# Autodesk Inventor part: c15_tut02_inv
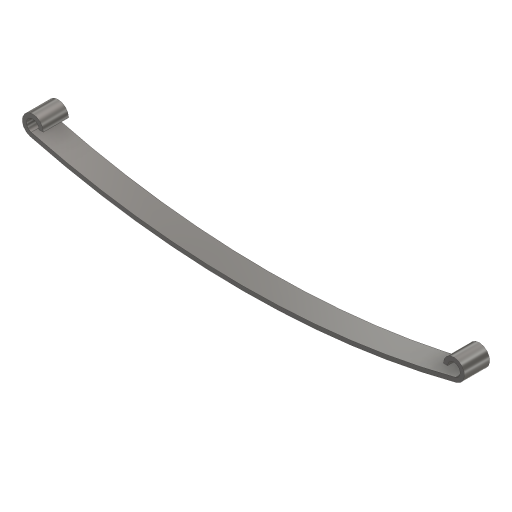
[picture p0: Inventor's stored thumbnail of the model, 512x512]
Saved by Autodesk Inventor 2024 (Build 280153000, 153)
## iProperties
Created: 2017-05
Part Number: c15_tut02_inv
Material: Steel, Mild
Document SubType Name: Modeling
Designer: CADCIM 00
Mass: 5.6491 g
Surface Area: 16.9114 cm^2
Volume: 0.71963 cm^3
Density: 7.85 g/cm^3
Appearance: Semi-Polished
Author: CADCIM 00
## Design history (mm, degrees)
sketch "Sketch1"
  geometry: L1 (0, 0)-(0, 18.068); L2 (48.5, 8.9)-(47.5, 8.9); L3 (-48.5, 8.9)-(-47.5, 8.9); A1 r 200 centre (0, 201) between (-50.378, 7.449) and (50.378, 7.449); A2 r 201 centre (0, 201) between (-50.63, 6.481) and (50.63, 6.481); A3 r 1.5 centre (50, 8.9) between (50.378, 7.449) and (48.5, 8.9); A4 r 2.5 centre (50, 8.9) between (50.63, 6.481) and (47.5, 8.9); A5 r 1.5 centre (-50, 8.9) between (-48.5, 8.9) and (-50.378, 7.449); A6 r 2.5 centre (-50, 8.9) between (-47.5, 8.9) and (-50.63, 6.481); 5 further points
  constraints: 13 point on circle, 6 centre point, 6 end point, 6 symmetric about line, 5 horizontal alignment, 3 coincident, 2 tangent, 1 horizontal, 1 midpoint, 1 vertical, 2 other
  dimensions: "d0" = 200 radius of A1; "d1" = 1 radial gap between concentric circles of A2 A1; "d2" = 2.5 radius of A4; "d3" = 50 distance from line of L1 A3.centre
extrude "Extrusion1" new body sketch "Sketch1" distance "d4" = 6; taper "d5" = 0 deg
body "Solid1"
